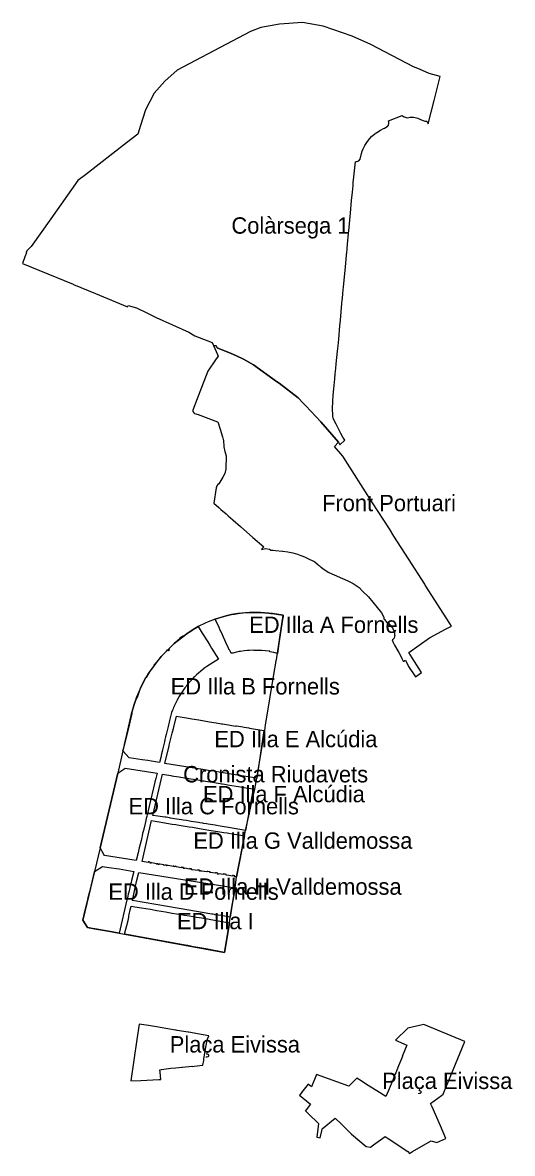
# Model space of a CAD drawing. Extents: x 599912 to 613490, y 4411003 to 4422920.
# Drawn here: x 607170 to 607529, y 4416361 to 4417189 of the extents above; entities that cross this region are included whole.
import ezdxf

# ---------------------------------------------------------------- set-up
doc = ezdxf.new("R2010")
doc.units = 0
for name, color, linetype in [('Estudi de Detall', 7, 'Continuous'), ('Sector amb disposicions transitòries', 7, 'Continuous'), ("Unitat d'Actuació", 7, 'Continuous')]:
    doc.layers.add(name, color=color, linetype=linetype)

msp = doc.modelspace()

# ---------------------------------------------------------------- linework, layer by layer
at = {"layer": 'Estudi de Detall'}
for points in [[(607311.52, 4416752.19), (607315.1, 4416753.29), (607316.21, 4416753.64), (607319.47, 4416754.64), (607322.52, 4416755.28), (607323.56, 4416755.49), (607325.25, 4416755.82), (607325.74, 4416755.91), (607326.83, 4416756.12), (607327.7, 4416756.29), (607328.04, 4416756.36), (607333.98, 4416756.99), (607334.11, 4416756.99), (607335.17, 4416757.05), (607336.77, 4416757.15), (607342.84, 4416757.11), (607343.27, 4416757.07), (607343.73, 4416757.04), (607344.26, 4416757.03), (607344.68, 4416757.03), (607344.8, 4416757.02), (607344.93, 4416757.01), (607350.67, 4416756.56), (607350.97, 4416756.53), (607351.45, 4416756.47), (607352.28, 4416756.4), (607352.8, 4416756.36), (607352.8, 4416756.35), (607353.48, 4416756.3), (607357.92, 4416755.65), (607361.45, 4416755.08), (607361.25, 4416753.82), (607361.24, 4416753.74), (607361.19, 4416753.45), (607361.13, 4416753.15), (607361.02, 4416752.56), (607360.97, 4416752.26), (607360.92, 4416751.98), (607360.96, 4416751.97), (607358.2, 4416734.25), (607357.93, 4416732.48), (607357.09, 4416727.09), (607357.08, 4416727.09), (607354.4, 4416727.72), (607351.69, 4416728.29), (607351.67, 4416728.61), (607348.46, 4416728.98), (607345.8, 4416729.23), (607343.08, 4416729.29), (607340.51, 4416729.29), (607339.92, 4416729.28), (607339.92, 4416729.47), (607336.32, 4416729.28), (607335.31, 4416729.29), (607332.77, 4416729.09), (607332.72, 4416729.08), (607330.2, 4416728.6), (607329.21, 4416728.45), (607328.1, 4416728.28), (607324.37, 4416727.26), (607324.24, 4416727.21), (607324.1, 4416727.18), (607323.97, 4416727.17), (607323.83, 4416727.17), (607323.69, 4416727.19), (607323.56, 4416727.23), (607323.43, 4416727.29), (607323.31, 4416727.36), (607323.2, 4416727.44), (607323.1, 4416727.54), (607323.02, 4416727.65), (607321.96, 4416729.76), (607321.8, 4416729.69), (607321.28, 4416730.84), (607319.37, 4416735.04), (607316.83, 4416740.67), (607315.63, 4416743.32), (607315.25, 4416744.17), (607314.33, 4416746.14)], [(607299.09, 4416746.76), (607302.1, 4416741.89), (607306.04, 4416735.53), (607307.77, 4416732.74), (607308.91, 4416730.89), (607313.92, 4416722.79), (607307.99, 4416719.26), (607305.35, 4416717.42), (607304.71, 4416716.97), (607303.9, 4416716.4), (607303.05, 4416715.79), (607302.38, 4416715.32), (607297.87, 4416711.36), (607297.03, 4416710.55), (607296.48, 4416710.01), (607295.76, 4416709.32), (607295.07, 4416708.65), (607291.16, 4416704.2), (607290.55, 4416703.45), (607289.94, 4416702.69), (607289.24, 4416701.77), (607288.77, 4416701.16), (607285.47, 4416696.07), (607284.97, 4416695.18), (607284.5, 4416694.35), (607284.01, 4416693.47), (607283.58, 4416692.69), (607280.95, 4416687.33), (607280.62, 4416686.44), (607280.26, 4416685.52), (607279.58, 4416683.72), (607278.06, 4416677.93), (607277.77, 4416676.72), (607277.54, 4416675.75), (607277.29, 4416674.73), (607277.02, 4416673.62), (607275.63, 4416667.73), (607275.2, 4416665.94), (607274.95, 4416664.93), (607274.72, 4416663.97), (607274.31, 4416662.24), (607272.86, 4416656.3), (607272.61, 4416655.26), (607272.19, 4416653.54), (607271.59, 4416650.79), (607270.74, 4416647.17), (607264.89, 4416648.09), (607262.19, 4416648.51), (607257.9, 4416649.18), (607248.4, 4416650.66), (607243.92, 4416655.63), (607244.3, 4416657.11), (607244.53, 4416658.06), (607245, 4416659.93), (607245.13, 4416660.48), (607245.32, 4416661.3), (607245.85, 4416663.55), (607246.35, 4416665.68), (607246.83, 4416667.71), (607249.91, 4416681.65), (607250.27, 4416683.1), (607250.42, 4416683.06), (607250.54, 4416684.01), (607250.69, 4416684.55), (607252.11, 4416689.54), (607253.82, 4416694.49), (607254.21, 4416694.33), (607254.32, 4416694.6), (607254.73, 4416695.62), (607256.97, 4416702.26), (607257.5, 4416703.26), (607260.81, 4416709.52), (607260.93, 4416709.49), (607261.59, 4416710.61), (607262.21, 4416711.66), (607272, 4416724.75), (607275.84, 4416728.84), (607276.6, 4416729.6), (607277.29, 4416728.91), (607277.99, 4416729.62), (607277.31, 4416730.3), (607281.37, 4416734.3), (607290.95, 4416741.64), (607292.4, 4416742.67), (607296.56, 4416745.33)], [(607283.07, 4416681.06), (607285.88, 4416680.5), (607290.52, 4416679.74), (607294.43, 4416679.1), (607299.47, 4416678.28), (607303.45, 4416677.63), (607307.29, 4416677.01), (607312.32, 4416676.19), (607316.17, 4416675.56), (607316.83, 4416675.44), (607321.27, 4416674.71), (607323.68, 4416674.31), (607326.72, 4416673.84), (607326.74, 4416674.03), (607327.24, 4416673.97), (607331.8, 4416673.2), (607332.74, 4416673.05), (607336.27, 4416672.46), (607336.76, 4416672.4), (607336.74, 4416672.29), (607347.1, 4416670.61), (607342.17, 4416635.56), (607326.07, 4416638.19), (607320.35, 4416639.11), (607314.51, 4416640.05), (607309.16, 4416641.02), (607309.12, 4416640.8), (607302.4, 4416641.94), (607274.71, 4416646.48), (607277.79, 4416659.37), (607277.92, 4416659.91), (607279.56, 4416666.65), (607280.04, 4416668.62), (607280.87, 4416672.02)], [(607240.1, 4416639.19), (607244.59, 4416642.29), (607245.62, 4416643.01), (607268.92, 4416639.2), (607268, 4416635.33), (607267.41, 4416632.86), (607267.38, 4416632.73), (607263.19, 4416615.18), (607261.9, 4416609.75), (607261.4, 4416607.67), (607261.36, 4416607.5), (607261.04, 4416606.15), (607260.72, 4416604.8), (607260.68, 4416604.66), (607260.18, 4416602.52), (607258.9, 4416597.17), (607258.38, 4416595), (607258.36, 4416594.9), (607258.04, 4416593.55), (607257.7, 4416592.13), (607257.18, 4416589.94), (607255.88, 4416584.48), (607255.37, 4416582.38), (607255.33, 4416582.22), (607255.02, 4416580.91), (607254.69, 4416579.51), (607254.56, 4416578.97), (607253.68, 4416575.25), (607230.53, 4416578.83), (607229.99, 4416579.75), (607227.16, 4416584.51)], [(607273.01, 4416638.56), (607274.41, 4416638.33), (607278.92, 4416637.59), (607279.87, 4416637.43), (607281.27, 4416637.21), (607285.21, 4416636.56), (607289.06, 4416635.93), (607290.47, 4416635.7), (607291.27, 4416635.57), (607292.26, 4416635.41), (607293.64, 4416635.18), (607293.77, 4416635.16), (607297.61, 4416634.54), (607301.39, 4416633.93), (607302.54, 4416633.75), (607303.54, 4416633.58), (607304.44, 4416633.44), (607305.85, 4416633.21), (607309.66, 4416632.59), (607313.74, 4416631.94), (607315.11, 4416631.72), (607316.08, 4416631.57), (607316.8, 4416631.45), (607318.26, 4416631.21), (607322.13, 4416630.59), (607328.51, 4416629.57), (607334.33, 4416628.61), (607339.43, 4416627.77), (607334.09, 4416598.49), (607333.83, 4416597.39), (607321.37, 4416599.47), (607316.74, 4416600.22), (607315.16, 4416600.49), (607312.54, 4416600.93), (607311.5, 4416601.07), (607306.5, 4416601.89), (607305.25, 4416602.1), (607302.85, 4416602.49), (607302.41, 4416602.57), (607300.28, 4416602.92), (607299.27, 4416603.08), (607293.91, 4416603.96), (607292.71, 4416604.15), (607290.4, 4416604.53), (607287.98, 4416604.92), (607286.91, 4416605.1), (607281.75, 4416605.94), (607278.9, 4416606.4), (607278.15, 4416606.52), (607275.6, 4416606.94), (607274.6, 4416607.1), (607269.47, 4416607.82), (607269.46, 4416607.82), (607265.78, 4416608.34)], [(607264.85, 4416604.51), (607267.46, 4416604.08), (607270.4, 4416603.6), (607273.15, 4416603.15), (607280.09, 4416602.02), (607282.74, 4416601.58), (607285.22, 4416601.18), (607292.37, 4416600.01), (607294.79, 4416599.61), (607297.26, 4416599.21), (607304.31, 4416598.06), (607306.99, 4416597.62), (607313.36, 4416596.58), (607317.82, 4416595.85), (607320.29, 4416595.45), (607325.49, 4416594.6), (607328.9, 4416594.04), (607333.02, 4416593.37), (607327.18, 4416563.33), (607326.52, 4416563.45), (607326.48, 4416563.23), (607325.78, 4416563.35), (607325.9, 4416564.03), (607325.01, 4416564.17), (607324.31, 4416564.29), (607324.24, 4416563.87), (607320, 4416564.56), (607319.58, 4416564.63), (607319.64, 4416565.04), (607319.35, 4416565.09), (607318.94, 4416565.16), (607318.11, 4416565.29), (607317.78, 4416565.34), (607317.41, 4416565.4), (607317.36, 4416565.07), (607314.56, 4416565.46), (607314.09, 4416565.53), (607314.05, 4416565.25), (607313.35, 4416565.36), (607313.46, 4416566.04), (607312.4, 4416566.21), (607311.7, 4416566.33), (607311.63, 4416565.93), (607308.17, 4416566.47), (607307.73, 4416566.54), (607307.8, 4416566.96), (607307.1, 4416567.07), (607306.24, 4416567.21), (607305.54, 4416567.32), (607305.47, 4416566.91), (607301.44, 4416567.55), (607301.24, 4416567.59), (607300.79, 4416567.66), (607300.74, 4416567.39), (607300.04, 4416567.51), (607300.15, 4416568.19), (607299.42, 4416568.31), (607298.72, 4416568.43), (607298.65, 4416568), (607295.16, 4416568.55), (607294.8, 4416568.61), (607294.76, 4416568.36), (607294.06, 4416568.48), (607294.11, 4416568.79), (607294.17, 4416569.16), (607293.39, 4416569.29), (607292.69, 4416569.4), (607292.63, 4416569.03), (607289.24, 4416569.58), (607288.94, 4416569.63), (607288.89, 4416569.31), (607288.19, 4416569.42), (607288.3, 4416570.11), (607287.41, 4416570.25), (607286.71, 4416570.37), (607286.66, 4416570.02), (607283.27, 4416570.56), (607282.94, 4416570.61), (607283, 4416570.97), (607282.3, 4416571.08), (607282.25, 4416570.76), (607281.41, 4416570.87), (607281.46, 4416571.21), (607281.33, 4416571.24), (607280.76, 4416571.33), (607280.7, 4416570.95), (607277.13, 4416571.53), (607276.45, 4416571.64), (607276.43, 4416571.48), (607276.2, 4416571.51), (607275.73, 4416571.59), (607275.75, 4416571.77), (607274.67, 4416571.94), (607274.64, 4416571.72), (607273.94, 4416571.83), (607273.97, 4416572.05), (607271.06, 4416572.51), (607270.56, 4416572.6), (607270.51, 4416572.28), (607269.81, 4416572.39), (607269.86, 4416572.73), (607269.12, 4416572.85), (607269.07, 4416572.51), (607268.37, 4416572.63), (607268.42, 4416572.95), (607265.08, 4416573.48), (607264.56, 4416573.56), (607264.52, 4416573.25), (607263.82, 4416573.36), (607263.93, 4416574.05), (607263.07, 4416574.19), (607262.37, 4416574.3), (607262.31, 4416573.93), (607258.05, 4416574.65)], [(607223.02, 4416567.01), (607223.08, 4416567.26), (607228.92, 4416570.91), (607233.58, 4416570.25), (607241.05, 4416569.07), (607251.83, 4416567.27), (607250.23, 4416560.55), (607249.9, 4416559.16), (607249.53, 4416557.64), (607248.22, 4416552.14), (607247.84, 4416550.57), (607247.52, 4416549.22), (607247.2, 4416547.87), (607246.87, 4416546.49), (607246.87, 4416546.47), (607241.07, 4416522), (607233.29, 4416523.38), (607230.31, 4416523.9), (607223.26, 4416525.21), (607223.13, 4416525.24), (607220.3, 4416525.76), (607217.92, 4416526.29), (607214.63, 4416531.51), (607216.34, 4416538.76), (607217.67, 4416544.39), (607219, 4416550.02), (607219.8, 4416553.38)], [(607255.56, 4416566.59), (607326.1, 4416555.23), (607326.05, 4416554.93), (607326, 4416554.63), (607325.95, 4416554.34), (607325.9, 4416554.04), (607325.86, 4416553.81), (607325.63, 4416552.44), (607324.09, 4416543.23), (607322.5, 4416533.74), (607315.85, 4416534.85), (607311.58, 4416535.57), (607310.91, 4416535.67), (607309.81, 4416535.85), (607309.13, 4416535.94), (607285.06, 4416540.19), (607250.91, 4416545.93), (607253.91, 4416559.78)], [(607249.94, 4416541.9), (607252.7, 4416541.43), (607257.44, 4416540.62), (607260.71, 4416540.06), (607264.03, 4416539.49), (607268.65, 4416538.7), (607271.89, 4416538.15), (607275.2, 4416537.58), (607280.02, 4416536.76), (607283.21, 4416536.21), (607286.34, 4416535.68), (607288.93, 4416535.28), (607292.76, 4416534.65), (607295.29, 4416534.24), (607297.78, 4416533.83), (607301.83, 4416533.17), (607302.97, 4416532.98), (607305.93, 4416532.47), (607308.35, 4416532.05), (607321.95, 4416529.71), (607321.94, 4416529.65), (607318.48, 4416507.92), (607304.56, 4416510.44), (607300.4, 4416511.19), (607298.78, 4416511.48), (607298, 4416511.62), (607297.31, 4416511.75), (607295.7, 4416512.04), (607295.28, 4416512.11), (607291.38, 4416512.88), (607291.06, 4416512.95), (607250.74, 4416520.33), (607249.37, 4416520.58), (607245.16, 4416521.35), (607247.7, 4416531.42), (607248.13, 4416533.82), (607248.29, 4416534.67), (607248.46, 4416535.65), (607249.3, 4416539.18)]]:
    msp.add_lwpolyline(points, close=True, dxfattribs=at)
at = {"layer": 'Sector amb disposicions transitòries'}
for points in [[(607432.67, 4417110.6), (607433.22, 4417110.87), (607435, 4417111.73), (607435.54, 4417112.05), (607437.57, 4417113.25), (607437.8, 4417113.39), (607438.49, 4417114.36), (607438.85, 4417115.48), (607438.89, 4417116.27), (607438.61, 4417117.54), (607448.49, 4417121.34), (607448.8, 4417121.15), (607449.95, 4417120.45), (607450.78, 4417120.08), (607451.57, 4417119.82), (607452.68, 4417119.78), (607454.38, 4417120.11), (607455.64, 4417120.22), (607456.9, 4417120.18), (607458.15, 4417119.99), (607459.97, 4417119.42), (607462.06, 4417118.47), (607463.9, 4417117.65), (607465.17, 4417117.32), (607465.46, 4417117.28), (607466.65, 4417117.16), (607467.68, 4417115.3), (607472.01, 4417132.46), (607476.44, 4417150.01), (607468.27, 4417152.19), (607461.38, 4417155.45), (607456.98, 4417157.09), (607425.63, 4417173.38), (607411.87, 4417179.44), (607390.67, 4417186.78), (607375.48, 4417189.46), (607358.59, 4417188.42), (607345.05, 4417185.85), (607337.49, 4417183.05), (607283.56, 4417154.68), (607274.62, 4417146.43), (607266.82, 4417137.73), (607260.53, 4417125.45), (607256.73, 4417114.05), (607254.84, 4417107.8), (607246.53, 4417101.33), (607216.44, 4417077.88), (607210.97, 4417073.63), (607191.16, 4417045.69), (607176.56, 4417025.38), (607175.66, 4417024.43), (607173.41, 4417022.07), (607172.89, 4417021), (607172.96, 4417020.95), (607173.27, 4417020.77), (607172.04, 4417017.69), (607170.41, 4417013), (607207.49, 4416997.63), (607207.59, 4416997.59), (607223.8, 4416990.86), (607247.24, 4416981.15), (607247.46, 4416981.55), (607247.72, 4416982.04), (607253.94, 4416980.32), (607261.84, 4416976.43), (607267.28, 4416973.75), (607268.29, 4416973.26), (607292.2, 4416962.45), (607296.56, 4416959.78), (607306.15, 4416956.18), (607309.39, 4416954.97), (607310.33, 4416952.8), (607312.19, 4416952.44), (607313.09, 4416951.16), (607323.19, 4416946.8), (607327.12, 4416945.1), (607332.3, 4416942.86), (607339.62, 4416938.64), (607356.55, 4416926.47), (607358.45, 4416925.11), (607372.32, 4416914.31), (607376.24, 4416910.23), (607377.96, 4416908.45), (607389.04, 4416896.94), (607401.86, 4416881.86), (607402.95, 4416880.05), (607406.53, 4416883.45), (607405.17, 4416885.65), (607403.53, 4416888.33), (607400.23, 4416895.01), (607398.09, 4416899.35), (607397.85, 4416901.12), (607397.63, 4416902.72), (607397.55, 4416905.39), (607397.52, 4416906.8), (607397.52, 4416906.87), (607397.69, 4416911.5), (607397.71, 4416911.91), (607398.08, 4416916.44), (607398.51, 4416920.92), (607399.23, 4416928.42), (607399.58, 4416932.06), (607399.95, 4416935.85), (607400.28, 4416939.24), (607401.18, 4416948.65), (607401.57, 4416952.66), (607402.03, 4416957.39), (607402.94, 4416967.32), (607403.31, 4416971.43), (607404.44, 4416983.69), (607404.67, 4416986.11), (607404.77, 4416987.26), (607405.12, 4416991.02), (607405.55, 4416995.67), (607406.71, 4417007.78), (607408.03, 4417021.41), (607408.17, 4417023), (607408.26, 4417023.87), (607408.57, 4417027.11), (607409.28, 4417034.86), (607409.68, 4417039.2), (607410.43, 4417047.27), (607410.66, 4417049.74), (607411.51, 4417059.01), (607412.08, 4417065.08), (607412.55, 4417070.14), (607412.77, 4417072.62), (607412.92, 4417074.21), (607414.46, 4417087.35), (607416.7, 4417088.03), (607417.75, 4417089.29), (607418.71, 4417093.62), (607419.2, 4417095.22), (607419.9, 4417096.9), (607421.26, 4417099.45), (607422.67, 4417101.63), (607423.1, 4417102.32), (607424.86, 4417104.62), (607426.39, 4417106.15), (607426.71, 4417106.48), (607428.67, 4417108.07), (607429.05, 4417108.39), (607429.69, 4417108.79), (607432.3, 4417110.43)], [(607449.46, 4416721.19), (607449.62, 4416721.3), (607449.81, 4416721.43), (607449.93, 4416721.22), (607450.44, 4416721.74), (607450.58, 4416721.81), (607450.97, 4416722.09), (607451.41, 4416721.21), (607453.29, 4416717.41), (607458.38, 4416709.81), (607462.7, 4416713), (607455.84, 4416723.92), (607453.46, 4416727.7), (607468.48, 4416738.44), (607480.25, 4416744.79), (607484.63, 4416747.15), (607483.5, 4416748.92), (607465.45, 4416777.18), (607465.1, 4416777.73), (607453.13, 4416796.47), (607442.54, 4416813.05), (607439.16, 4416818.35), (607426.88, 4416837.57), (607405.1, 4416871.67), (607398.91, 4416878.83), (607401.86, 4416881.86), (607389.04, 4416896.94), (607377.96, 4416908.45), (607376.24, 4416910.23), (607372.32, 4416914.31), (607358.45, 4416925.11), (607356.55, 4416926.47), (607339.62, 4416938.64), (607332.3, 4416942.86), (607327.12, 4416945.1), (607323.19, 4416946.8), (607313.09, 4416951.16), (607312.19, 4416952.44), (607310.33, 4416952.8), (607310.32, 4416952.8), (607313.18, 4416946.18), (607313.68, 4416945.02), (607311.8, 4416942.28), (607311.79, 4416942.27), (607311.77, 4416942.24), (607306.11, 4416934.01), (607301.45, 4416921.9), (607295.07, 4416905.34), (607295.25, 4416904.43), (607295.86, 4416903.44), (607296.44, 4416902.9), (607299.17, 4416902.11), (607313.29, 4416896.83), (607313.58, 4416896.72), (607315.22, 4416891.41), (607316.85, 4416885.78), (607317.4, 4416883.9), (607317.51, 4416883.51), (607317.97, 4416878.61), (607318.72, 4416875.01), (607319.63, 4416871.86), (607319.53, 4416868.44), (607319.45, 4416865.8), (607319.41, 4416864.51), (607319.34, 4416862.23), (607318.51, 4416858.91), (607317.14, 4416856.27), (607314.14, 4416851.47), (607313.54, 4416851.01), (607312.85, 4416850.02), (607312.19, 4416848.4), (607310.46, 4416837.23), (607314.24, 4416833.93), (607315.77, 4416832.6), (607319.49, 4416829.35), (607321.1, 4416827.94), (607324.38, 4416825.08), (607329.97, 4416820.2), (607339.2, 4416812.15), (607347.07, 4416805.28), (607345.79, 4416803.62), (607345.55, 4416803.3), (607348.31, 4416803.99), (607351.09, 4416803.6), (607351.23, 4416803.58), (607351.95, 4416802.92), (607352.14, 4416802.74), (607354.05, 4416802.68), (607355.63, 4416802.63), (607360.94, 4416802.14), (607361.18, 4416802.12), (607364.89, 4416801.48), (607368.39, 4416800.87), (607371.88, 4416799.71), (607374.3, 4416798.84), (607374.96, 4416798.61), (607377.07, 4416797.87), (607380.98, 4416796.04), (607382.58, 4416795.3), (607383.66, 4416794.79), (607383.88, 4416794.69), (607384.56, 4416794.15), (607386.46, 4416792.59), (607387.08, 4416792.04), (607387.66, 4416791.53), (607388.79, 4416790.53), (607389, 4416790.32), (607389.11, 4416790.21), (607389.39, 4416789.98), (607389.43, 4416789.94), (607390.35, 4416789.32), (607394.35, 4416786.64), (607394.84, 4416786.37), (607408.86, 4416780.19), (607412.71, 4416778.37), (607413.45, 4416777.88), (607416.29, 4416776), (607417.06, 4416775.47), (607419.56, 4416772.72), (607423.8, 4416768.44), (607430.22, 4416760.81), (607432.47, 4416757.97), (607433.42, 4416756.76), (607435.11, 4416753.71), (607435.21, 4416752.94), (607435.15, 4416752.45), (607435.58, 4416751.92), (607437.41, 4416749.66), (607437.72, 4416749.27), (607437.94, 4416749.5), (607438.15, 4416749.71), (607441.43, 4416745.71), (607442.06, 4416744.68), (607442.29, 4416744.14), (607442.51, 4416743.65), (607442.53, 4416743.58), (607442.54, 4416743.56), (607442.64, 4416743.24), (607442.91, 4416742.33), (607442.99, 4416741.75), (607443.05, 4416741.4), (607443.06, 4416741.2), (607443.07, 4416741.06), (607443.06, 4416740.84), (607443.08, 4416740.25), (607443.02, 4416739.77), (607443.02, 4416739.77), (607442.93, 4416739.1), (607442.74, 4416738.51), (607442.64, 4416738.21), (607442.49, 4416737.93), (607442.29, 4416737.67), (607442.05, 4416737.45), (607441.78, 4416737.27), (607441.49, 4416737.14), (607441.28, 4416737.09), (607441.18, 4416737.06), (607442.07, 4416735.1), (607442.97, 4416733.14), (607445.34, 4416728.92), (607446.05, 4416727.65), (607447.26, 4416725.56), (607448.36, 4416723.38), (607449.31, 4416721.49)], [(607322.5, 4416533.74), (607326.1, 4416555.23), (607327.18, 4416563.33), (607329.75, 4416576.7), (607333.02, 4416593.37), (607333.83, 4416597.39), (607336.1, 4416608), (607338.97, 4416620.42), (607340.58, 4416627.59), (607342.17, 4416635.56), (607347.85, 4416670.49), (607348.5, 4416674.48), (607354.83, 4416713.12), (607355.95, 4416719.81), (607356.33, 4416722.12), (607356.34, 4416722.19), (607356.35, 4416722.36), (607361.45, 4416755.08), (607353.48, 4416756.3), (607344.8, 4416757.02), (607336.77, 4416757.15), (607328.04, 4416756.36), (607323.56, 4416755.49), (607319.47, 4416754.64), (607311.52, 4416752.19), (607306.37, 4416750.16), (607304.16, 4416749.13), (607299.09, 4416746.76), (607296.56, 4416745.33), (607292.4, 4416742.67), (607287.95, 4416739.5), (607287.82, 4416739.68), (607285.48, 4416737.91), (607285.6, 4416737.75), (607281.37, 4416734.3), (607277.31, 4416730.31), (607275.84, 4416728.84), (607272.04, 4416724.71), (607268.54, 4416720.67), (607268.43, 4416720.77), (607266.68, 4416718.37), (607266.78, 4416718.3), (607263.66, 4416714.12), (607260.93, 4416709.49), (607260.81, 4416709.52), (607256.97, 4416702.26), (607254.76, 4416697.32), (607253.7, 4416694.54), (607253.82, 4416694.49), (607252.11, 4416689.54), (607250.54, 4416684.01), (607250.42, 4416683.06), (607247.74, 4416671.31), (607243.92, 4416655.63), (607240.1, 4416639.19), (607227.16, 4416584.51), (607223.08, 4416567.26), (607214.63, 4416531.51), (607217.92, 4416526.29), (607223.13, 4416525.24), (607233.29, 4416523.38), (607241.07, 4416522), (607245.16, 4416521.35), (607318.48, 4416507.92), (607321.95, 4416529.71)], [(607302.53, 4416425.35), (607303.1, 4416428.67), (607303.3, 4416429.85), (607305.6, 4416443.75), (607306.87, 4416446.86), (607306.86, 4416446.87), (607298.58, 4416448.33), (607292.34, 4416449.39), (607291.68, 4416449.51), (607283.65, 4416450.78), (607282.91, 4416450.9), (607282.39, 4416450.98), (607276.76, 4416451.89), (607268.48, 4416453.26), (607262.56, 4416454.23), (607255.87, 4416455.34), (607255.86, 4416455.33), (607254.18, 4416444.15), (607249.64, 4416413.9), (607249.61, 4416413.7), (607249.78, 4416413.71), (607257.13, 4416414.08), (607270.26, 4416414.75), (607271.61, 4416414.82), (607271.66, 4416414.82), (607271.15, 4416420.2), (607270.99, 4416421.87), (607271.83, 4416421.99), (607272.14, 4416422.03), (607279.13, 4416422.96), (607282.75, 4416423.34), (607286.99, 4416423.76), (607287.03, 4416423.76), (607287.23, 4416423.78), (607287.62, 4416423.81), (607287.63, 4416423.81), (607287.64, 4416423.81), (607294.52, 4416424.6), (607294.54, 4416424.6), (607294.55, 4416424.6), (607294.6, 4416424.28), (607294.6, 4416424.28), (607296.13, 4416424.48)]]:
    msp.add_lwpolyline(points, close=True, dxfattribs=at)
at = {"layer": "Unitat d'Actuació"}
msp.add_lwpolyline([(607470.45, 4416394.81), (607470.44, 4416394.8), (607469.42, 4416397.16), (607477.3, 4416403.07), (607478.63, 4416404.07), (607479.66, 4416406.55), (607481.29, 4416410.48), (607482.05, 4416412.3), (607487.69, 4416425.9), (607494.53, 4416442.68), (607464.39, 4416454.99), (607452.78, 4416452.3), (607443.71, 4416443.47), (607452.07, 4416439.91), (607448.62, 4416431.64), (607448.91, 4416431.52), (607445.87, 4416424.68), (607444.58, 4416421.59), (607443.81, 4416419.73), (607443.29, 4416418.5), (607442.18, 4416415.56), (607440.98, 4416412.66), (607438.49, 4416406.71), (607436.69, 4416402.39), (607429.93, 4416406.42), (607422.43, 4416411.19), (607418.56, 4416413.66), (607415.33, 4416415.84), (607409.59, 4416409.92), (607385.69, 4416418.52), (607382.19, 4416409.33), (607379.56, 4416411.34), (607374.71, 4416405.29), (607374.97, 4416405.19), (607373.28, 4416403.16), (607381.36, 4416396.69), (607377.59, 4416391.56), (607377.71, 4416391.71), (607379.98, 4416389.54), (607387.27, 4416382.44), (607385.92, 4416372.44), (607388.42, 4416372), (607389.66, 4416377.24), (607390.04, 4416378.53), (607399.39, 4416386.52), (607403.85, 4416382.28), (607411.35, 4416374.59), (607422.12, 4416365.74), (607425.27, 4416365.26), (607427.56, 4416366.81), (607436.05, 4416372.88), (607438.29, 4416371.52), (607452.82, 4416362.1), (607454.02, 4416360.6), (607456.24, 4416361.9), (607464.28, 4416366.64), (607469.76, 4416369.87), (607473.85, 4416368.68), (607480.6, 4416371.48), (607476.59, 4416380.82)], close=True, dxfattribs=at)

# ---------------------------------------------------------------- texts
at = {"layer": 'Estudi de Detall'}
for s, p in [('ED Illa A Fornells', (607336.48, 4416742.12)), ('ED Illa B Fornells', (607278.92, 4416696.97)), ('ED Illa E Alcúdia', (607310.91, 4416658.31)), ('ED Illa F Alcúdia', (607302.61, 4416617.98)), ('ED Illa C Fornells', (607248.04, 4416609.13)), ('ED Illa G Valldemossa', (607295.54, 4416583.87)), ('ED Illa H Valldemossa ', (607288.51, 4416550.17)), ('ED Illa D Fornells', (607233.23, 4416546.46)), ('ED Illa I', (607283.56, 4416524.91))]:
    msp.add_text(s, height=12, dxfattribs=at).set_placement(p)
at = {"layer": 'Sector amb disposicions transitòries'}
for s, p in [('Colàrsega 1', (607323.42, 4417034.75)), ('Front Portuari', (607389.85, 4416831.31)), ('Cronista Riudavets', (607288.04, 4416632.54)), ('Plaça Eivissa', (607278.24, 4416434.52))]:
    msp.add_text(s, height=12, dxfattribs=at).set_placement(p)
at = {"layer": "Unitat d'Actuació"}
msp.add_text('Plaça Eivissa', height=12, dxfattribs=at).set_placement((607433.9, 4416407.79))

doc.saveas('drawing.dxf')
